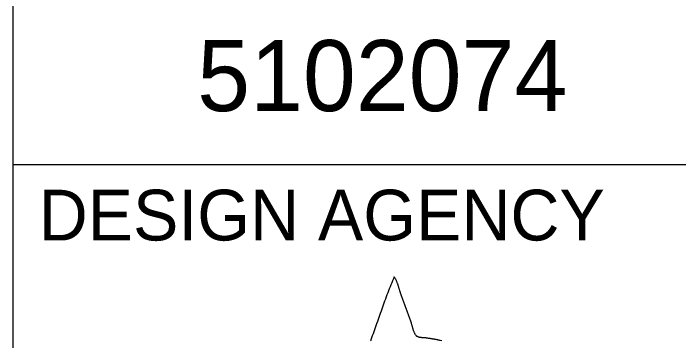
# Model space of a CAD drawing. Extents: x 0 to 34, y 0 to 22.
# Drawn here: x 32 to 33.31, y 4.652 to 5.298 of the extents above; entities that cross this region are included whole.
import ezdxf

# ---------------------------------------------------------------- set-up
doc = ezdxf.new("R2010")
doc.units = 0
for name, color, linetype in [('BR_P_Brg_Pad_Object', 7, 'Continuous'), ('BR_X_Brg_Centerline', 7, 'Continuous'), ('SH_Data', 7, 'Continuous')]:
    doc.layers.add(name, color=color, linetype=linetype)

msp = doc.modelspace()

# ---------------------------------------------------------------- linework, layer by layer
at = {"layer": 'BR_P_Brg_Pad_Object'}
for points in [[(32.7502, 4.7781), (32.7485, 4.7743), (32.7468, 4.7704), (32.7451, 4.7665), (32.7435, 4.7625), (32.742, 4.7585), (32.7404, 4.7546), (32.7388, 4.7506), (32.7372, 4.7466), (32.7357, 4.7426), (32.7342, 4.7386), (32.7326, 4.7346), (32.7312, 4.7306), (32.7297, 4.7265), (32.7283, 4.7225), (32.7268, 4.7185), (32.7254, 4.7144), (32.724, 4.7104), (32.7226, 4.7063), (32.7211, 4.7023), (32.7197, 4.6982), (32.7183, 4.6941), (32.7169, 4.6901), (32.7154, 4.686), (32.7141, 4.682), (32.7126, 4.678), (32.7112, 4.674), (32.7098, 4.6699), (32.7084, 4.6659), (32.7069, 4.6619), (32.7055, 4.6579), (32.704, 4.654)], [(32.7626, 4.7464), (32.7622, 4.7474), (32.7618, 4.7483), (32.7616, 4.7493), (32.7612, 4.7503), (32.761, 4.7514), (32.7606, 4.7524), (32.7603, 4.7535), (32.76, 4.7546), (32.7597, 4.7556), (32.7593, 4.7568), (32.7591, 4.7579), (32.7587, 4.759), (32.7583, 4.7601), (32.758, 4.7612), (32.7576, 4.7623), (32.7572, 4.7634), (32.7569, 4.7644), (32.7565, 4.7655), (32.7561, 4.7666), (32.7557, 4.7677), (32.7553, 4.7687), (32.7548, 4.7698), (32.7545, 4.7708), (32.754, 4.7718), (32.7535, 4.7728), (32.753, 4.7738), (32.7525, 4.7746), (32.7519, 4.7756), (32.7514, 4.7764), (32.7508, 4.7773), (32.7502, 4.7781)], [(32.7826, 4.6909), (32.782, 4.6927), (32.7814, 4.6945), (32.7806, 4.6962), (32.78, 4.698), (32.7793, 4.6998), (32.7787, 4.7016), (32.778, 4.7033), (32.7774, 4.7052), (32.7766, 4.707), (32.776, 4.7087), (32.7753, 4.7105), (32.7747, 4.7123), (32.774, 4.7141), (32.7734, 4.7158), (32.7728, 4.7176), (32.772, 4.7195), (32.7714, 4.7213), (32.7708, 4.723), (32.7701, 4.7248), (32.7695, 4.7266), (32.7689, 4.7284), (32.7682, 4.7301), (32.7675, 4.732), (32.7669, 4.7338), (32.7663, 4.7356), (32.7656, 4.7374), (32.765, 4.7391), (32.7644, 4.7409), (32.7638, 4.7427), (32.7632, 4.7446), (32.7626, 4.7464)], [(32.7948, 4.661), (32.7942, 4.6616), (32.7936, 4.6622), (32.793, 4.6628), (32.7924, 4.6636), (32.7919, 4.6643), (32.7913, 4.6652), (32.7908, 4.6661), (32.7903, 4.667), (32.7899, 4.6679), (32.7895, 4.669), (32.789, 4.67), (32.7886, 4.6711), (32.7883, 4.6722), (32.7878, 4.6733), (32.7874, 4.6744), (32.7871, 4.6756), (32.7868, 4.6767), (32.7865, 4.6779), (32.7861, 4.679), (32.7859, 4.6801), (32.7855, 4.6813), (32.7851, 4.6824), (32.7849, 4.6835), (32.7846, 4.6845), (32.7843, 4.6855), (32.784, 4.6865), (32.7838, 4.6875), (32.7834, 4.6884), (32.7832, 4.6893), (32.7829, 4.6901), (32.7826, 4.6909)], [(32.704, 4.654), (32.7037, 4.653), (32.7033, 4.6521)], [(32.8108, 4.658), (32.8103, 4.658), (32.8099, 4.6581), (32.8094, 4.6581), (32.8089, 4.6581), (32.8084, 4.6582), (32.8078, 4.6582), (32.8073, 4.6582), (32.8067, 4.6582), (32.8062, 4.6584), (32.8056, 4.6584), (32.805, 4.6584), (32.8045, 4.6584), (32.8039, 4.6585), (32.8033, 4.6585), (32.8028, 4.6586), (32.8022, 4.6586), (32.8016, 4.6587), (32.8011, 4.6587), (32.8005, 4.6588), (32.8, 4.659), (32.7994, 4.6591), (32.7989, 4.6592), (32.7985, 4.6593), (32.7979, 4.6595), (32.7974, 4.6597), (32.7969, 4.6598), (32.7965, 4.6601), (32.796, 4.6603), (32.7956, 4.6605), (32.7952, 4.6608), (32.7948, 4.661)], [(32.8405, 4.6529), (32.8396, 4.6531), (32.8387, 4.6533), (32.8377, 4.6535), (32.8368, 4.6538), (32.8358, 4.6539), (32.8348, 4.6541), (32.8339, 4.6542), (32.8329, 4.6545), (32.8319, 4.6546), (32.8311, 4.6548), (32.8301, 4.655), (32.8291, 4.6552), (32.8282, 4.6553), (32.8272, 4.6556), (32.8262, 4.6557), (32.8253, 4.6559), (32.8243, 4.6561), (32.8233, 4.6562), (32.8223, 4.6564), (32.8214, 4.6565), (32.8204, 4.6567), (32.8194, 4.6568), (32.8185, 4.657), (32.8175, 4.6571), (32.8165, 4.6573), (32.8156, 4.6574), (32.8147, 4.6575), (32.8137, 4.6576), (32.8128, 4.6578), (32.8118, 4.6579), (32.8108, 4.658)], [(32.8436, 4.6523), (32.8405, 4.6529)]]:
    msp.add_lwpolyline(points, dxfattribs=at)
at = {"layer": 'BR_X_Brg_Centerline'}
for p, q in [((32, 0.5), (32, 21.5)), ((32, 5), (33.5, 5))]:
    msp.add_line(p, q, dxfattribs=at)

# ---------------------------------------------------------------- texts
at = {"layer": 'SH_Data'}
for s, height, p in [('5102074', 0.14, (32.3621, 5.105)), ('DESIGN AGENCY', 0.1, (32.05, 4.85))]:
    msp.add_text(s, height=height, dxfattribs=at).set_placement(p)

doc.saveas('drawing.dxf')
